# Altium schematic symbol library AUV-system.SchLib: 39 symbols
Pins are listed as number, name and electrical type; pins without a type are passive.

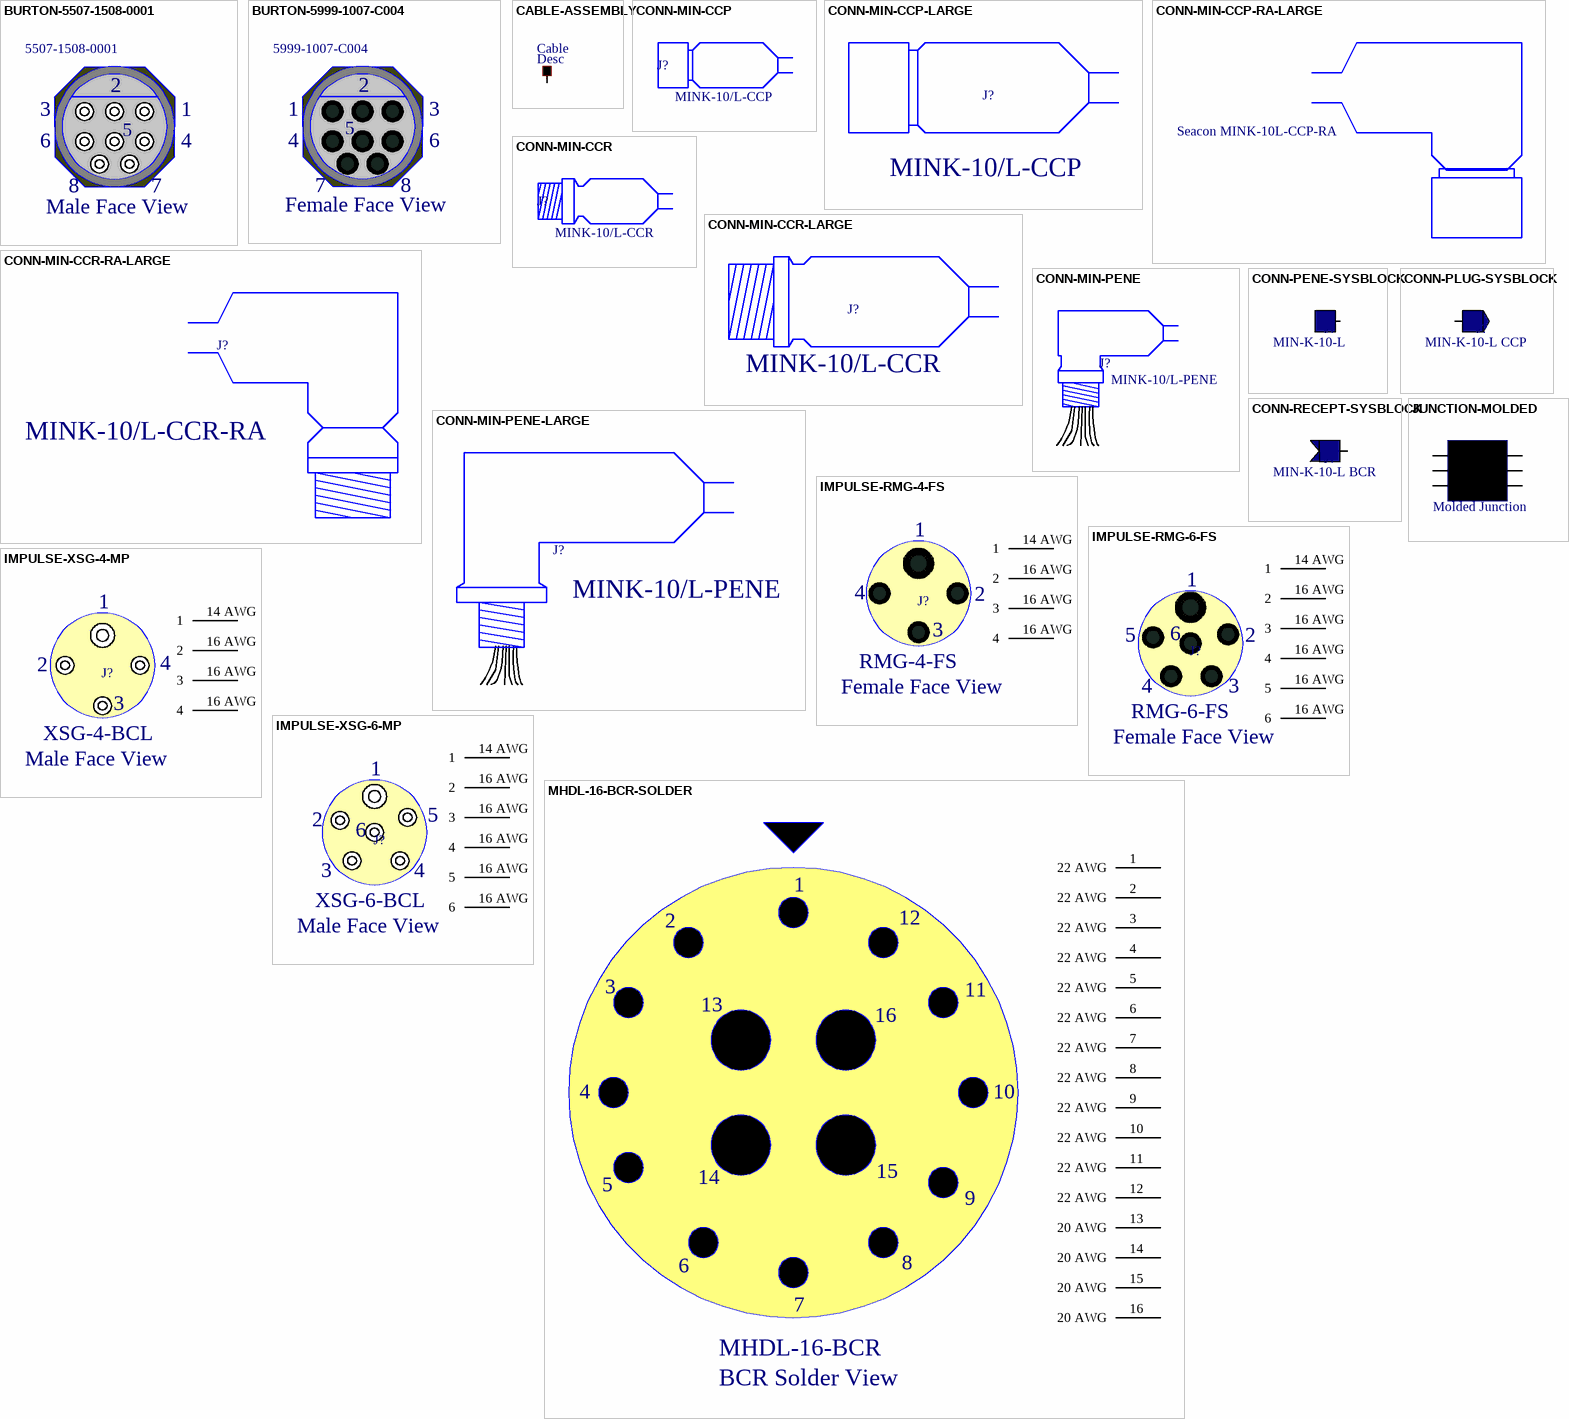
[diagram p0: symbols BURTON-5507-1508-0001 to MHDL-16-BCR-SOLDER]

## BURTON-5507-1508-0001
designator J?, comment 5507-1508-0001
Burton 8 Pin Male BH Connector

## BURTON-5999-1007-C004
designator J?, comment 5999-1007-C004
Burton 8 Socket Female IL Connector

## CABLE-ASSEMBLY
designator J?, comment Cable  DescSheet: Desc
Cable Assembly
pins: 0 "Pointer"

## CONN-MIN-CCP
designator J?, comment MINK-10/L-CCP
Seacon MIN Connector CCP

## CONN-MIN-CCP-LARGE
designator J?, comment MINK-10/L-CCP
Seacon MIN Connector CCP

## CONN-MIN-CCP-RA-LARGE
designator *, comment Seacon MINK-10L-CCP-RA

## CONN-MIN-CCR
designator J?, comment MINK-10/L-CCR
Seacon MIN Connector CCR

## CONN-MIN-CCR-LARGE
designator J?, comment MINK-10/L-CCR
Seacon MIN Connector CCR

## CONN-MIN-CCR-RA-LARGE
designator J?, comment MINK-10/L-CCR-RA
Seacon MIN Connector CCR Right Angle

## CONN-MIN-PENE
designator J?, comment MINK-10/L-PENE
Seacon MIN Penetrator

## CONN-MIN-PENE-LARGE
designator J?, comment MINK-10/L-PENE
Seacon MIN Penetrator

## CONN-PENE-SYSBLOCK
designator J?, comment MIN-K-10-L
Pene Symbol; Manufacturer: Seacon
pins: 0

## CONN-PLUG-SYSBLOCK
designator J?, comment MIN-K-10-L CCP
Plug Symbol; Manufacturer: Seacon
pins: 0

## CONN-RECEPT-SYSBLOCK
designator J?, comment MIN-K-10-L BCR
Recept Symbol; Manufacturer: Seacon
pins: 0

## IMPULSE-RMG-4-FS
designator J?, comment RMG-4-FS
Impulse RMG Connector
pins: 14 AWG 1, 16 AWG 2, 16 AWG 3, 16 AWG 4

## IMPULSE-RMG-6-FS
designator J?, comment RMG-6-FS
Impulse RMG Connector
pins: 14 AWG 1, 16 AWG 2, 16 AWG 3, 16 AWG 4, 16 AWG 5, 16 AWG 6

## IMPULSE-XSG-4-MP
designator J?, comment XSG-4-BCL
Impulse XSG Connector; ManufPartNo: XSG-4-MP
pins: 14 AWG 1, 16 AWG 2, 16 AWG 3, 16 AWG 4

## IMPULSE-XSG-6-MP
designator J?, comment XSG-6-BCL
Impulse XSG Connector; ManufPartNo: XSG-6-MP
pins: 14 AWG 1, 16 AWG 2, 16 AWG 3, 16 AWG 4, 16 AWG 5, 16 AWG 6

## JUNCTION-MOLDED
designator J?, comment Molded Junction
pins: 1, 2, 3, 4, 5, 6

## MHDL-16-BCR-SOLDER
designator J?, comment MHDL-16-BCR
Impulse MHDL 16 BCR
pins: 1 22 AWG, 2 22 AWG, 3 22 AWG, 4 22 AWG, 5 22 AWG, 6 22 AWG, 7 22 AWG, 8 22 AWG, 9 22 AWG, 10 22 AWG, 11 22 AWG, 12 22 AWG, 13 20 AWG, 14 20 AWG, 15 20 AWG, 16 20 AWG

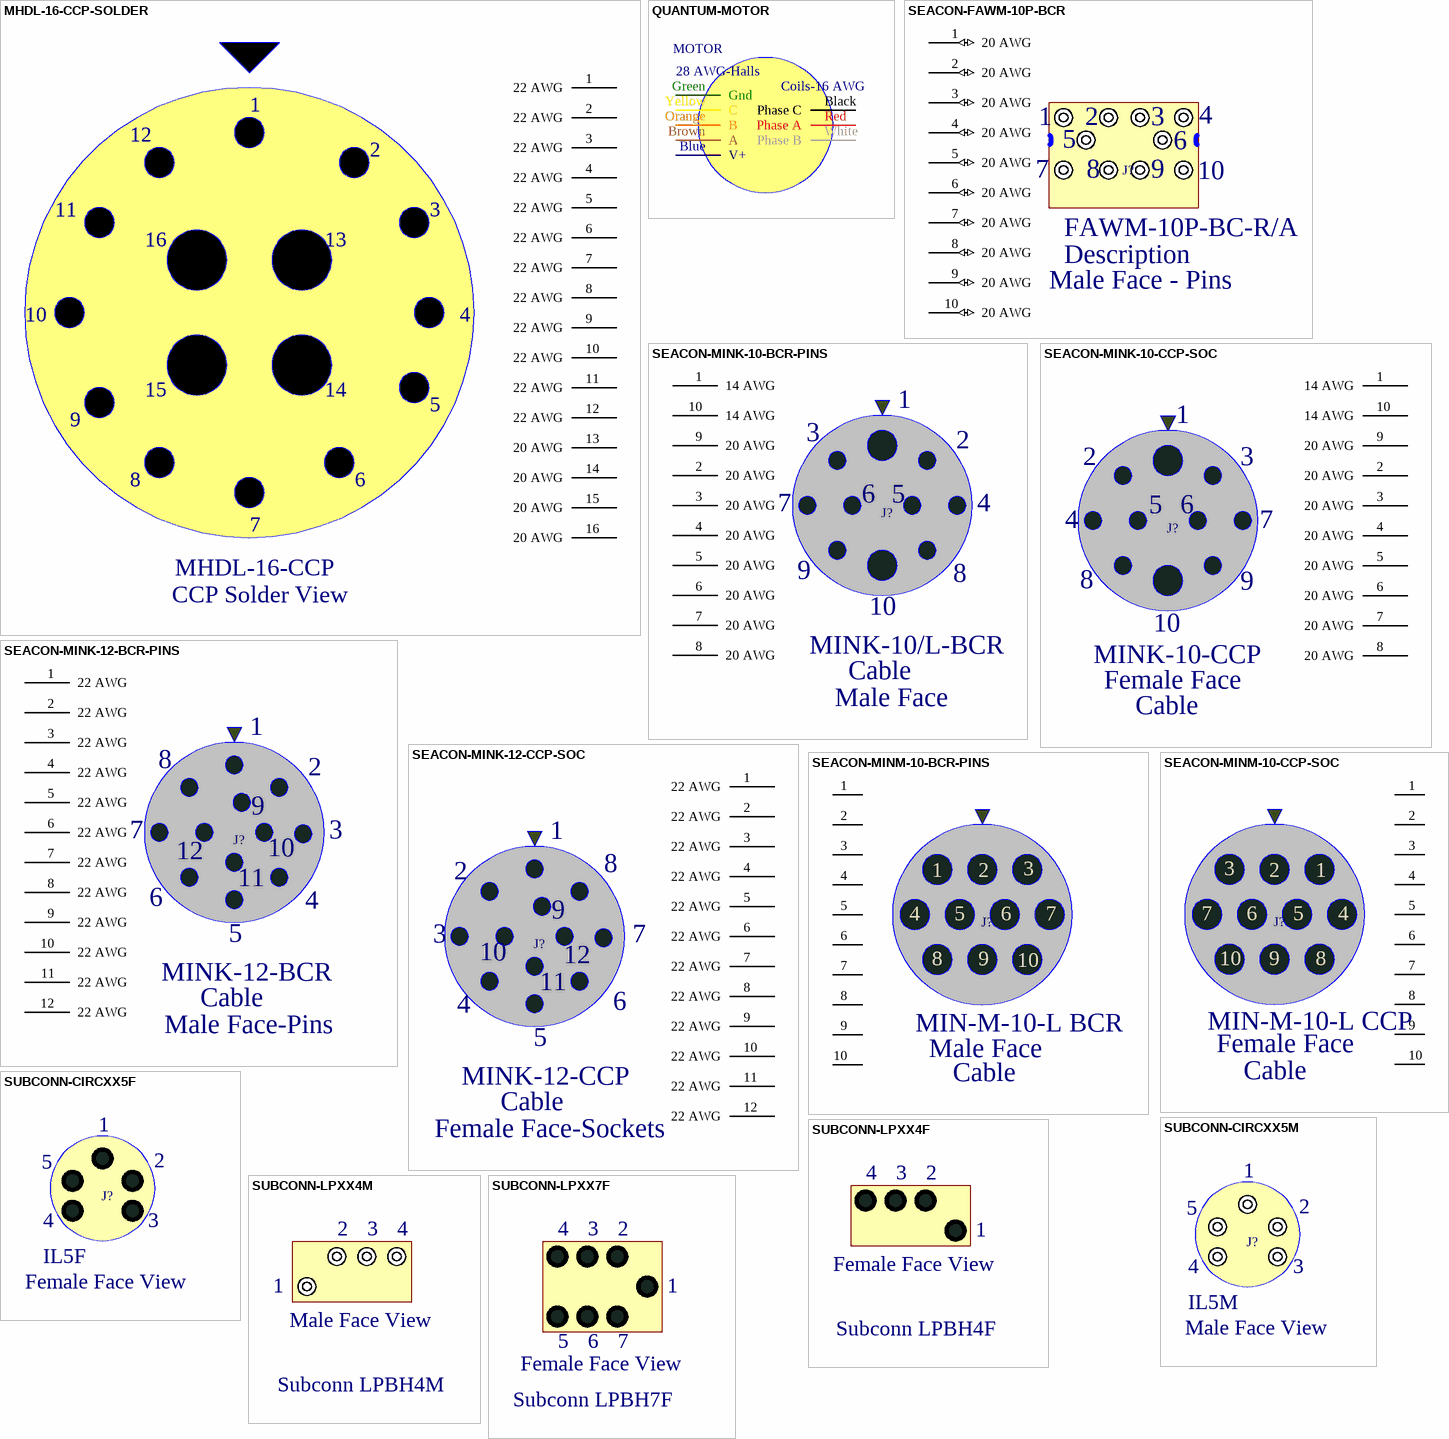
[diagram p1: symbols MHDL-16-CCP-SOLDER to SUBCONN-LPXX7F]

## MHDL-16-CCP-SOLDER
designator J?, comment MHDL-16-CCP
Impulse MHDL 16 CCP
pins: 1 22 AWG, 2 22 AWG, 3 22 AWG, 4 22 AWG, 5 22 AWG, 6 22 AWG, 7 22 AWG, 8 22 AWG, 9 22 AWG, 10 22 AWG, 11 22 AWG, 12 22 AWG, 13 20 AWG, 14 20 AWG, 15 20 AWG, 16 20 AWG

## QUANTUM-MOTOR
designator ?, comment MOTOR
Quantum Motor
pins: Black Phase C (power), Blue V+ (power), Brown A (power), Green Gnd (power), Orange B (power), Red Phase A (power), White Phase B (power), Yellow C (power)

## SEACON-FAWM-10P-BCR
designator J?, comment FAWM-10P-BC-R/A  View: Male Face - Pins  DescSheet: Description
Seacon FAWM-10P-BC-R/A Connector
pins: 1 20 AWG (io), 2 20 AWG (io), 3 20 AWG (io), 4 20 AWG (io), 5 20 AWG (io), 6 20 AWG (io), 7 20 AWG (io), 8 20 AWG (io), 9 20 AWG (io), 10 20 AWG (io)

## SEACON-MINK-10-BCR-PINS
designator J?, comment MINK-10/L-BCR  DescSheet: Cable  View: Male Face
Seacon MINK-10/L-BCR Connector
pins: 1 14 AWG, 2 20 AWG, 3 20 AWG, 4 20 AWG, 5 20 AWG, 6 20 AWG, 7 20 AWG, 8 20 AWG, 9 20 AWG, 10 14 AWG

## SEACON-MINK-10-CCP-SOC
designator J?, comment MINK-10-CCP  DescSheet: Cable  View: Female Face
Seacon MINK-10/L-CCP Connector
pins: 1 14 AWG, 2 20 AWG, 3 20 AWG, 4 20 AWG, 5 20 AWG, 6 20 AWG, 7 20 AWG, 8 20 AWG, 9 20 AWG, 10 14 AWG

## SEACON-MINK-12-BCR-PINS
designator J?, comment MINK-12-BCR  DescSheet: Cable  View: Male Face-Pins
Seacon MINK-12-BCR Connector
pins: 1 22 AWG, 2 22 AWG, 3 22 AWG, 4 22 AWG, 5 22 AWG, 6 22 AWG, 7 22 AWG, 8 22 AWG, 9 22 AWG, 10 22 AWG, 11 22 AWG, 12 22 AWG

## SEACON-MINK-12-CCP-SOC
designator J?, comment MINK-12-CCP  DescSheet: Cable  View: Female Face-Sockets
Seacon MINK-12-CCP Connector
pins: 1 22 AWG, 2 22 AWG, 3 22 AWG, 4 22 AWG, 5 22 AWG, 6 22 AWG, 7 22 AWG, 8 22 AWG, 9 22 AWG, 10 22 AWG, 11 22 AWG, 12 22 AWG

## SEACON-MINM-10-BCR-PINS
designator J?, comment MIN-M-10-L BCR  DescSheet: Cable  View: Male Face
Seacon MINM-10/L-BCR Connector
pins: 1, 2, 3, 4, 5, 6, 7, 8, 9, 10

## SEACON-MINM-10-CCP-SOC
designator J?, comment MIN-M-10-L CCP  DescSheet: Cable  View: Female Face
Seacon MINM-10/L-CCP Connector
pins: 1, 2, 3, 4, 5, 6, 7, 8, 9, 10

## SUBCONN-CIRCXX5F
designator J?, comment IL5F
Subconn IL5F Connector

## SUBCONN-CIRCXX5M
designator J?, comment IL5M
Subconn IL5M Connector

## SUBCONN-LPXX4F
designator J?, comment DescSheet: Subconn LPBH4F  (hidden comment: LPXX4F)
Subconn LPxx4F Connector; DescSheet: Subconn LPIL4F

## SUBCONN-LPXX4M
designator J?, comment DescSheet: Subconn LPBH4M  (hidden comment: LPXX4M)
Subconn LPxx4M Connector; DescSheet: Subconn LPIL4M

## SUBCONN-LPXX7F
designator J?, comment DescSheet: Subconn LPBH7F  (hidden comment: LPXX7F)
Subconn LPxx7F Connector; DescSheet: Subconn LPIL7F

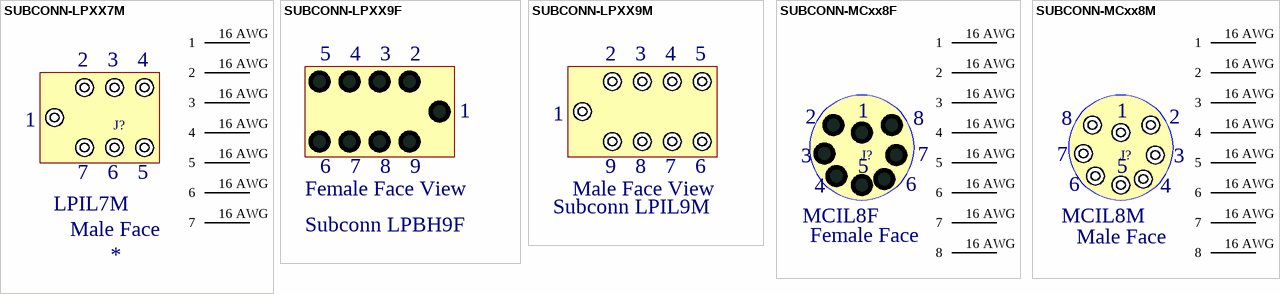
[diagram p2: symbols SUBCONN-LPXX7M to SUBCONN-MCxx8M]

## SUBCONN-LPXX7M
designator J?, comment LPIL7M  View: Male Face
Subconn LPxx7M Connector
pins: 16 AWG 1, 16 AWG 2, 16 AWG 3, 16 AWG 4, 16 AWG 5, 16 AWG 6, 16 AWG 7

## SUBCONN-LPXX9F
designator J?, comment DescSheet: Subconn LPBH9F  (hidden comment: LPXX9F)
Subconn LPxx9F Connector; DescSheet: Subconn LPIL9F

## SUBCONN-LPXX9M
designator J?, comment DescSheet: Subconn LPIL9M  (hidden comment: LPXX9M)
Subconn LPxx9F Connector; DescSheet: Subconn LPBH9M

## SUBCONN-MCxx8F
designator J?, comment MCIL8F  View: Female Face
Subconn MCIL8F Connector
pins: 16 AWG 1, 16 AWG 2, 16 AWG 3, 16 AWG 4, 16 AWG 5, 16 AWG 6, 16 AWG 7, 16 AWG 8

## SUBCONN-MCxx8M
designator J?, comment MCIL8M  View: Male Face
Subconn MCIL8M Connector
pins: 16 AWG 1, 16 AWG 2, 16 AWG 3, 16 AWG 4, 16 AWG 5, 16 AWG 6, 16 AWG 7, 16 AWG 8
